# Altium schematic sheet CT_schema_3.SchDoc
size 282 x 169 mm
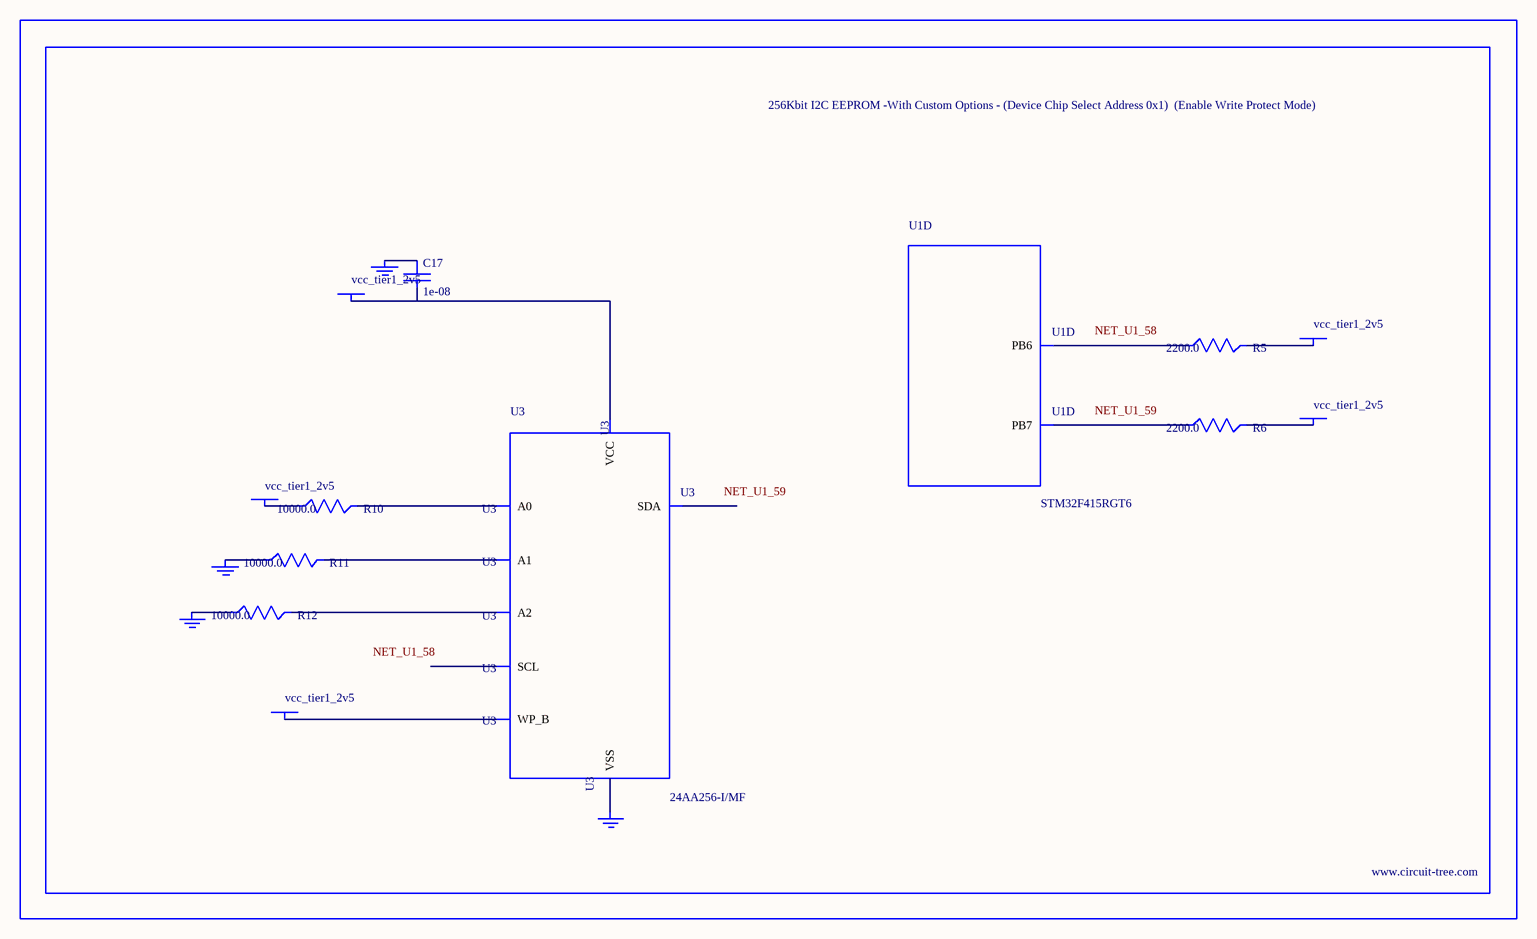
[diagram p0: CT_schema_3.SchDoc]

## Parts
BORDER2  (no value)
C17  1e-08  [C0402]
GND_INSTANCE_2_0  (no value)
GND_INSTANCE_2_1  (no value)
GND_INSTANCE_2_2  (no value)
GND_INSTANCE_2_3  (no value)
POWER_INSTANCE_2_0  vcc_tier1_2v5
POWER_INSTANCE_2_1  vcc_tier1_2v5
POWER_INSTANCE_2_2  vcc_tier1_2v5
POWER_INSTANCE_2_3  vcc_tier1_2v5
POWER_INSTANCE_2_4  vcc_tier1_2v5
R5  2200.0  [R0603]
R6  2200.0  [R0603]
R10  10000.0  [R0603]
R11  10000.0  [R0603]
R12  10000.0  [R0603]
U1  STM32F415RGT6  [LQFP64]  (part D of 7)
U3  24AA256-I/MF  [DFN8-S]

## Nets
NetC17_1: C17.1 GND_INSTANCE_2_2.0(GND)
NetC17_2: C17.2 POWER_INSTANCE_2_2.0(PWR) U3.8(VCC)
NetGND_INSTANCE_2_0_0: GND_INSTANCE_2_0.0(GND) R11.1
NetGND_INSTANCE_2_1_0: GND_INSTANCE_2_1.0(GND) R12.1
NetGND_INSTANCE_2_3_0: GND_INSTANCE_2_3.0(GND) U3.4(VSS)
NetPOWER_INSTANCE_2_0_0: POWER_INSTANCE_2_0.0(PWR) R10.1
NetPOWER_INSTANCE_2_1_0: POWER_INSTANCE_2_1.0(PWR) U3.7(WP_B)
NetPOWER_INSTANCE_2_3_0: POWER_INSTANCE_2_3.0(PWR) R5.2
NetPOWER_INSTANCE_2_4_0: POWER_INSTANCE_2_4.0(PWR) R6.2
NetR5_1: R5.1 U1.58(PB6)
NetR6_1: R6.1 U1.59(PB7)
NetR10_2: R10.2 U3.1(A0)
NetR11_2: R11.2 U3.2(A1)
NetR12_2: R12.2 U3.3(A2)

Not connected (* = marked no-connect by the designer): U3 5(SDA) 6(SCL)

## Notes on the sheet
- Labels drawn without touching a wire or pin: NET_U1_58, NET_U1_59

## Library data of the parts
BORDER2 = BORDER_PAGE2
C17 = C0402C103K3RAC
GND_INSTANCE_2_0-GND_INSTANCE_2_3 = GND
POWER_INSTANCE_2_0-POWER_INSTANCE_2_4 = PWR
R5 R6 = RC0603JR-072K2L
R10-R12 = RC0603JR-0710KL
